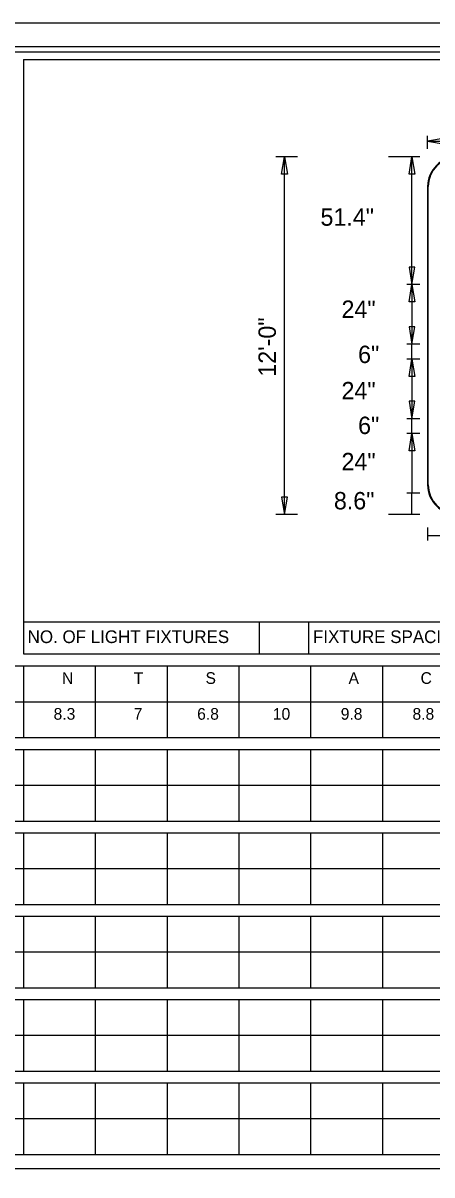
# Model space of a CAD drawing. Extents: x 17890628 to 17891459, y 17897314 to 17897992.
# Drawn here: x 17890724.69 to 17890738.41, y 17897458.18 to 17897496.82 of the extents above; entities that cross this region are included whole.
import ezdxf

# ---------------------------------------------------------------- set-up
doc = ezdxf.new("R2010")
doc.units = 0
for name, color, linetype in [('GSColorFill', 7, 'Continuous'), ('GSDims', 7, 'Continuous'), ('GSOutline', 7, 'Continuous'), ('PlotBorder_dp', 7, 'Continuous'), ('SheetBorder_dp', 7, 'Continuous'), ('SheetLinesMisc2_dp', 7, 'Continuous'), ('TextMinor', 7, 'Continuous'), ('XSCell', 7, 'Continuous')]:
    doc.layers.add(name, color=color, linetype=linetype)

msp = doc.modelspace()

# ---------------------------------------------------------------- linework, layer by layer
at = {"layer": 'GSColorFill'}
for p, q in [((17890738.263, 17897491.33), (17890738.263, 17897481.33)), ((17890738.263, 17897491.33), (17890738.263, 17897481.33)), ((17890738.263, 17897491.33), (17890738.263, 17897481.33)), ((17890738.277, 17897481.33), (17890738.277, 17897491.33))]:
    msp.add_line(p, q, dxfattribs=at)
for centre, radius, start, end in [((17890739.263, 17897491.33), 1, 90, 180), ((17890739.263, 17897491.33), 1, 90, 180), ((17890739.263, 17897491.33), 1, 90, 180), ((17890739.263, 17897491.33), 0.985, 90, 180), ((17890739.263, 17897481.33), 1, 180, 270), ((17890739.263, 17897481.33), 1, 180, 270), ((17890739.263, 17897481.33), 1, 180, 270), ((17890739.263, 17897481.33), 0.985, 180, 270)]:
    msp.add_arc(centre, radius, start, end, dxfattribs=at)
at = {"layer": 'GSDims'}
for p, q in [((17890738.263, 17897492.593), (17890738.263, 17897493.03)), ((17890738.263, 17897492.855), (17890752.763, 17897492.855)), ((17890738.263, 17897492.593), (17890738.263, 17897492.593)), ((17890733.9, 17897492.33), (17890733.171, 17897492.33)), ((17890733.462, 17897480.33), (17890733.462, 17897492.33)), ((17890738, 17897492.33), (17890736.95, 17897492.33)), ((17890738, 17897492.33), (17890737.563, 17897492.33)), ((17890737.738, 17897488.046), (17890737.738, 17897492.33)), ((17890738, 17897488.046), (17890737.563, 17897488.046)), ((17890738, 17897488.046), (17890737.563, 17897488.046)), ((17890737.738, 17897488.046), (17890737.738, 17897486.042)), ((17890738, 17897486.042), (17890737.563, 17897486.042)), ((17890738, 17897486.042), (17890737.563, 17897486.042)), ((17890737.738, 17897485.546), (17890737.738, 17897486.042)), ((17890738, 17897485.546), (17890737.563, 17897485.546)), ((17890738, 17897485.546), (17890737.563, 17897485.546)), ((17890737.738, 17897485.546), (17890737.738, 17897483.546)), ((17890738, 17897483.546), (17890737.563, 17897483.546)), ((17890738, 17897483.546), (17890737.563, 17897483.546)), ((17890737.738, 17897483.049), (17890737.738, 17897483.546)), ((17890738, 17897483.049), (17890737.563, 17897483.049)), ((17890738, 17897483.049), (17890737.563, 17897483.049)), ((17890737.738, 17897483.049), (17890737.738, 17897481.049)), ((17890738, 17897481.049), (17890737.563, 17897481.049)), ((17890738, 17897481.049), (17890737.563, 17897481.049)), ((17890737.738, 17897480.33), (17890737.738, 17897481.049)), ((17890733.9, 17897480.33), (17890733.171, 17897480.33)), ((17890738, 17897480.33), (17890736.95, 17897480.33)), ((17890738, 17897480.33), (17890737.563, 17897480.33)), ((17890738.263, 17897479.893), (17890738.263, 17897479.455)), ((17890738.263, 17897479.893), (17890738.263, 17897479.455)), ((17890738.263, 17897479.63), (17890739.429, 17897479.63))]:
    msp.add_line(p, q, dxfattribs=at)
for points in [[(17890738.263, 17897492.855), (17890738.846, 17897492.758), (17890738.846, 17897492.952)], [(17890733.462, 17897492.33), (17890733.56, 17897491.747), (17890733.365, 17897491.747)], [(17890737.738, 17897492.33), (17890737.835, 17897491.747), (17890737.641, 17897491.747)], [(17890737.738, 17897488.046), (17890737.835, 17897488.629), (17890737.641, 17897488.629)], [(17890737.738, 17897488.046), (17890737.835, 17897487.462), (17890737.641, 17897487.462)], [(17890737.738, 17897486.042), (17890737.835, 17897486.625), (17890737.641, 17897486.625)], [(17890737.738, 17897485.546), (17890737.835, 17897484.962), (17890737.641, 17897484.962)], [(17890737.738, 17897483.546), (17890737.835, 17897484.129), (17890737.641, 17897484.129)], [(17890737.738, 17897483.049), (17890737.835, 17897482.466), (17890737.641, 17897482.466)], [(17890733.462, 17897480.33), (17890733.56, 17897480.914), (17890733.365, 17897480.914)]]:
    msp.add_lwpolyline(points, close=True, dxfattribs=at)
at = {"layer": 'GSOutline'}
msp.add_line((17890738.263, 17897491.33), (17890738.263, 17897481.33), dxfattribs=at)
for centre, start, end in [((17890739.263, 17897491.33), 90, 180), ((17890739.263, 17897481.33), 180, 270)]:
    msp.add_arc(centre, 1, start, end, dxfattribs=at)
at = {"layer": 'PlotBorder_dp'}
msp.add_lwpolyline([(17890701.346, 17897413.687), (17890830.745, 17897413.687), (17890830.745, 17897496.818), (17890701.346, 17897496.818)], close=True, dxfattribs=at)
at = {"layer": 'SheetBorder_dp'}
msp.add_line((17890705.659, 17897496.034), (17890826.432, 17897496.034), dxfattribs=at)
at = {"layer": 'SheetLinesMisc2_dp'}
for p, q in [((17890705.872, 17897495.849), (17890826.223, 17897495.849)), ((17890724.706, 17897495.599), (17890765.638, 17897495.599)), ((17890724.706, 17897495.599), (17890724.706, 17897475.661)), ((17890724.706, 17897476.729), (17890765.638, 17897476.729)), ((17890732.613, 17897476.729), (17890732.613, 17897475.661)), ((17890734.269, 17897476.729), (17890734.269, 17897475.661)), ((17890724.706, 17897475.661), (17890765.638, 17897475.661)), ((17890706.449, 17897475.25), (17890765.638, 17897475.25)), ((17890724.706, 17897475.25), (17890724.706, 17897472.846)), ((17890727.114, 17897475.25), (17890727.114, 17897472.846)), ((17890729.521, 17897475.25), (17890729.521, 17897472.846)), ((17890731.929, 17897475.25), (17890731.929, 17897472.846)), ((17890734.337, 17897475.25), (17890734.337, 17897472.846)), ((17890736.745, 17897475.25), (17890736.745, 17897472.846)), ((17890706.449, 17897474.048), (17890765.638, 17897474.048)), ((17890706.449, 17897472.846), (17890765.638, 17897472.846)), ((17890706.449, 17897472.453), (17890765.638, 17897472.453)), ((17890724.706, 17897472.453), (17890724.706, 17897470.049)), ((17890727.114, 17897472.453), (17890727.114, 17897470.049)), ((17890729.521, 17897472.453), (17890729.521, 17897470.049)), ((17890731.929, 17897472.453), (17890731.929, 17897470.049)), ((17890734.337, 17897472.453), (17890734.337, 17897470.049)), ((17890736.745, 17897472.453), (17890736.745, 17897470.049)), ((17890706.449, 17897471.251), (17890765.638, 17897471.251)), ((17890706.449, 17897470.049), (17890765.638, 17897470.049)), ((17890706.449, 17897469.657), (17890765.638, 17897469.657)), ((17890724.706, 17897469.657), (17890724.706, 17897467.252)), ((17890727.114, 17897469.657), (17890727.114, 17897467.252)), ((17890729.521, 17897469.657), (17890729.521, 17897467.252)), ((17890731.929, 17897469.657), (17890731.929, 17897467.252)), ((17890734.337, 17897469.657), (17890734.337, 17897467.252)), ((17890736.745, 17897469.657), (17890736.745, 17897467.252)), ((17890706.449, 17897468.454), (17890765.638, 17897468.454)), ((17890706.449, 17897467.252), (17890765.638, 17897467.252)), ((17890706.449, 17897466.86), (17890765.638, 17897466.86)), ((17890724.706, 17897466.86), (17890724.706, 17897464.455)), ((17890727.114, 17897466.86), (17890727.114, 17897464.455)), ((17890729.521, 17897466.86), (17890729.521, 17897464.455)), ((17890731.929, 17897466.86), (17890731.929, 17897464.455)), ((17890734.337, 17897466.86), (17890734.337, 17897464.455)), ((17890736.745, 17897466.86), (17890736.745, 17897464.455)), ((17890706.449, 17897465.658), (17890765.638, 17897465.658)), ((17890706.449, 17897464.455), (17890765.638, 17897464.455)), ((17890706.449, 17897464.063), (17890765.638, 17897464.063)), ((17890724.706, 17897464.063), (17890724.706, 17897461.659)), ((17890727.114, 17897464.063), (17890727.114, 17897461.659)), ((17890729.521, 17897464.063), (17890729.521, 17897461.659)), ((17890731.929, 17897464.063), (17890731.929, 17897461.659)), ((17890734.337, 17897464.063), (17890734.337, 17897461.659)), ((17890736.745, 17897464.063), (17890736.745, 17897461.659)), ((17890706.449, 17897462.861), (17890765.638, 17897462.861)), ((17890706.449, 17897461.659), (17890765.638, 17897461.659)), ((17890706.449, 17897461.267), (17890765.638, 17897461.267)), ((17890724.706, 17897461.267), (17890724.706, 17897458.862)), ((17890727.114, 17897461.267), (17890727.114, 17897458.862)), ((17890729.521, 17897461.267), (17890729.521, 17897458.862)), ((17890731.929, 17897461.267), (17890731.929, 17897458.862)), ((17890734.337, 17897461.267), (17890734.337, 17897458.862)), ((17890736.745, 17897461.267), (17890736.745, 17897458.862)), ((17890706.449, 17897460.065), (17890765.638, 17897460.065)), ((17890706.449, 17897458.862), (17890765.638, 17897458.862)), ((17890705.872, 17897458.39), (17890826.223, 17897458.39))]:
    msp.add_line(p, q, dxfattribs=at)
at = {"layer": 'XSCell'}
msp.add_line((17890738.263, 17897491.33), (17890738.263, 17897481.33), dxfattribs=at)
for centre, start, end in [((17890739.263, 17897491.33), 90, 180), ((17890739.263, 17897481.33), 180, 270)]:
    msp.add_arc(centre, 1, start, end, dxfattribs=at)

# ---------------------------------------------------------------- texts
at = {"layer": 'GSDims'}
for s, height, p in [('51.4"', 0.5833, (17890734.668, 17897490.018)), ('24"', 0.5833, (17890735.373, 17897486.927)), ('6"', 0.5833, (17890735.93, 17897485.412)), ('24"', 0.5833, (17890735.373, 17897484.196)), ('6"', 0.5833, (17890735.93, 17897483.031)), ('24"', 0.5833, (17890735.373, 17897481.815)), ('8.6"', 0.5833, (17890735.118, 17897480.503)), ('N', 0.392, (17890725.994, 17897474.649)), ('T', 0.392, (17890728.402, 17897474.649)), ('S', 0.392, (17890730.811, 17897474.649)), ('A', 0.392, (17890735.609, 17897474.649)), ('C', 0.392, (17890738.026, 17897474.649)), ('8.3', 0.3921, (17890725.714, 17897473.447)), ('7', 0.392, (17890728.402, 17897473.447)), ('6.8', 0.3921, (17890730.531, 17897473.447)), ('10', 0.3921, (17890733.07, 17897473.447)), ('9.8', 0.3921, (17890735.347, 17897473.447)), ('8.8', 0.3921, (17890737.755, 17897473.447))]:
    msp.add_text(s, height=height, dxfattribs=at).set_placement(p)
msp.add_text('12\'-0"', height=0.5833, rotation=90, dxfattribs=at).set_placement((17890733.171, 17897484.955))
at = {"layer": 'TextMinor'}
for s, p in [('NO. OF LIGHT FIXTURES', (17890724.844, 17897476.019)), ('FIXTURE SPACING', (17890734.417, 17897476.019))]:
    msp.add_text(s, height=0.42516, dxfattribs=at).set_placement(p)

doc.saveas('drawing.dxf')
